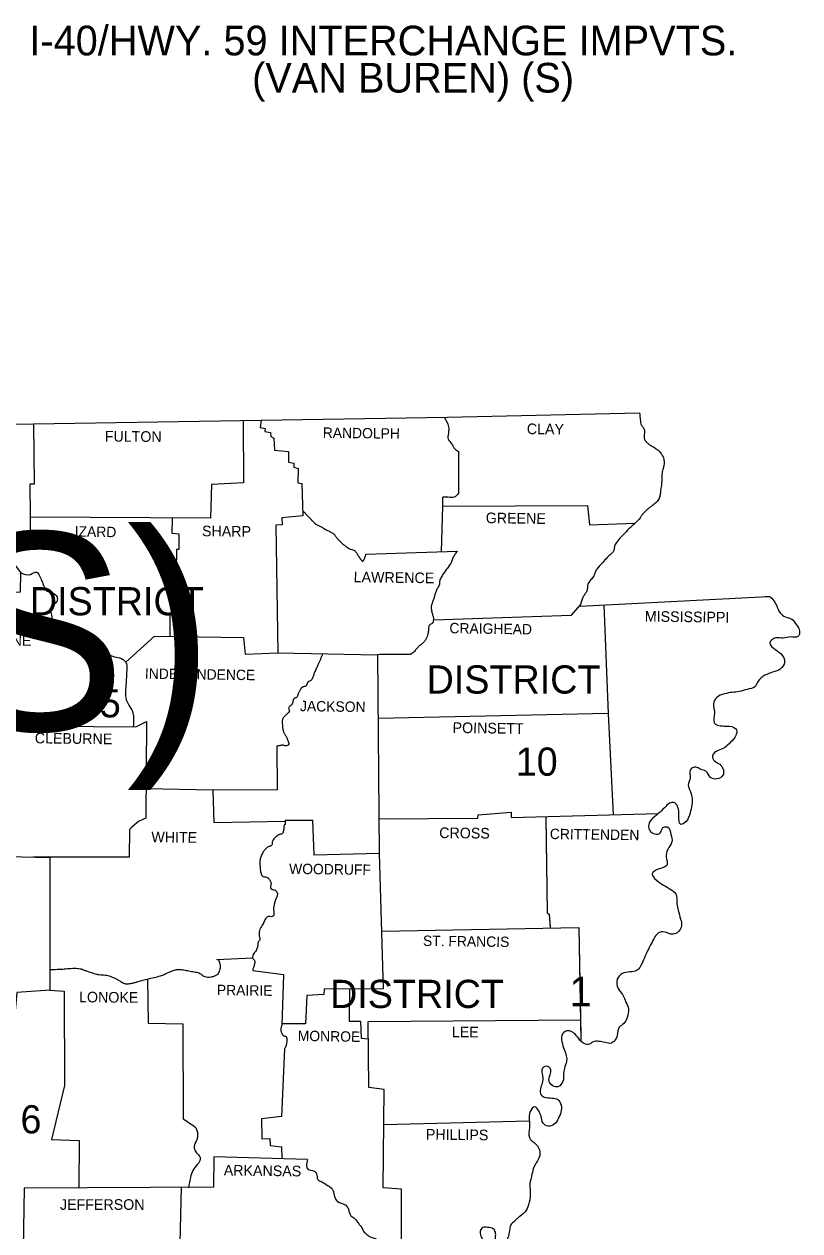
# Model space of a CAD drawing. Extents: x 535214 to 694517, y 381272 to 484355.
# Drawn here: x 674649 to 690329, y 455929 to 480321 of the extents above; entities that cross this region are included whole.
import ezdxf

# ---------------------------------------------------------------- set-up
doc = ezdxf.new("R2010")
doc.units = 0
for name, color, linetype in [('1', 7, 'Continuous'), ('Default', 7, 'Continuous'), ('G-ANNO-TEXT', 7, 'Continuous'), ('Level 8', 7, 'Continuous')]:
    doc.layers.add(name, color=color, linetype=linetype)

msp = doc.modelspace()

# ---------------------------------------------------------------- linework, layer by layer
at = {"layer": '1'}
for p, q in [((685889, 468559), (685943, 468725)), ((679929, 464229), (680488, 464229))]:
    msp.add_line(p, q, dxfattribs=at)
for points in [[(659659, 472234), (667744, 472229), (674839, 472244), (683209, 472374), (687089, 472464)], [(674839, 472244), (674849, 471024), (674764, 471019), (674779, 469774), (674429, 469724), (674459, 469389), (674579, 469234), (674569, 468839), (673889, 468814), (673864, 468204), (673244, 468184), (673214, 467444), (673249, 467384), (673264, 466204), (674334, 466134), (674319, 463499), (675169, 463474), (675169, 460794), (674499, 460744), (674449, 460154), (673324, 460149)], [(679438, 472315), (679419, 472164), (679519, 472149), (679514, 472089), (679629, 472064), (679639, 471984), (679694, 471949), (679709, 471709), (679994, 471679), (679994, 471464), (680099, 471449), (680099, 471364), (680189, 471339), (680184, 471049), (680264, 471034), (680284, 470379), (679859, 470339), (679864, 470199), (679734, 470194), (679779, 467614), (681794, 467569), (681829, 463559), (680514, 463524), (680488, 464229)], [(685889, 468559), (689684, 468754)], [(679929, 464229), (679929, 464144), (679904, 464139)], [(681823, 464259), (683819, 464269), (683824, 464339), (684494, 464389), (684494, 464284), (687473, 464366)], [(678544, 461414), (679264, 461449)], [(679269, 461189), (679894, 461109), (679859, 460089)], [(679914, 459609), (679854, 458239), (679444, 458194), (679454, 457789), (679619, 457794), (679624, 457654), (679849, 457629), (679857, 457388)], [(680374, 457374), (678484, 457424), (678474, 456809), (674650, 456794)]]:
    msp.add_lwpolyline(points, dxfattribs=at)
for points in [[(687089, 472464), (687094, 472409), (687100, 472353), (687106, 472299), (687114, 472244), (687126, 472213), (687146, 472185), (687168, 472158), (687184, 472129), (687191, 472078), (687185, 472023), (687181, 471969), (687184, 471943), (687194, 471919), (687232, 471870), (687279, 471829), (687315, 471805), (687352, 471784), (687389, 471763), (687424, 471739), (687497, 471675), (687527, 471637), (687541, 471616), (687554, 471594), (687573, 471551), (687583, 471509), (687587, 471466), (687584, 471424), (687576, 471380), (687563, 471337), (687552, 471293), (687544, 471249), (687542, 471200), (687540, 471151), (687538, 471102), (687534, 471054), (687514, 470884), (687505, 470806), (687497, 470767), (687492, 470748), (687484, 470729), (687432, 470659), (687364, 470604), (687336, 470581), (687307, 470559), (687278, 470537), (687249, 470514), (687144, 470409), (687125, 470382), (687108, 470353), (687091, 470324), (687069, 470299), (686939, 470179), (686809, 470054), (686704, 469944), (686676, 469911), (686649, 469876), (686624, 469840), (686599, 469804), (686584, 469766), (686577, 469725), (686568, 469684), (686561, 469665), (686549, 469649), (686522, 469620), (686492, 469593), (686463, 469567), (686434, 469539), (686344, 469439), (686224, 469304), (686205, 469273), (686191, 469238), (686179, 469203), (686164, 469169), (686138, 469129), (686106, 469092), (686075, 469054), (686049, 469014), (686039, 468978), (686036, 468939), (686033, 468900), (686024, 468864), (686008, 468833), (685988, 468803), (685968, 468774), (685949, 468744), (685943, 468725)], [(689629, 468749), (689684, 468754), (689854, 468574), (689929, 468424), (690039, 468339), (690164, 468294), (690259, 468179), (690324, 468054), (690289, 467944), (690149, 467934), (689994, 467909), (689844, 467914), (689724, 467814), (689834, 467679), (689979, 467554), (690019, 467419), (689939, 467289), (689779, 467219), (689624, 467159), (689484, 467039), (689419, 466924), (689264, 466874), (689104, 466829), (688964, 466814), (688804, 466784), (688649, 466709), (688584, 466579), (688604, 466394), (688599, 466199), (688764, 466134), (688909, 466129), (689049, 466054), (689034, 465944), (688929, 465804), (688804, 465694), (688679, 465639), (688564, 465534), (688604, 465429), (688709, 465359), (688784, 465244), (688774, 465139), (688654, 465064), (688524, 465094), (688429, 465219), (688319, 465259), (688224, 465304), (688114, 465239), (688114, 465094), (688074, 464939), (688109, 464824), (688154, 464664), (688149, 464544), (688109, 464374), (688024, 464199), (687924, 464144), (687884, 464334), (687864, 464489), (687804, 464579), (687724, 464584), (687619, 464509), (687504, 464394), (687359, 464269), (687274, 464144), (687319, 463989), (687429, 463949), (687514, 463979), (687559, 464079), (687644, 464094), (687724, 463939)], [(679904, 464139), (679901, 464097), (679898, 464056), (679891, 464015), (679886, 463994), (679883, 463984), (679879, 463974), (679863, 463956), (679838, 463947), (679809, 463940), (679796, 463936), (679784, 463929), (679726, 463877), (679674, 463819), (679665, 463795), (679663, 463768), (679660, 463741), (679649, 463719), (679640, 463711), (679630, 463706), (679605, 463698), (679580, 463691), (679559, 463679), (679536, 463655), (679514, 463630), (679493, 463603), (679474, 463574), (679440, 463503), (679419, 463429), (679415, 463354), (679419, 463279), (679423, 463236), (679429, 463193), (679439, 463151), (679446, 463130), (679454, 463109), (679478, 463089), (679513, 463083), (679549, 463079), (679579, 463064), (679589, 463053), (679599, 463041), (679615, 463016), (679639, 462964), (679641, 462938), (679633, 462911), (679627, 462884), (679629, 462859), (679653, 462837), (679687, 462825), (679723, 462813), (679749, 462789), (679758, 462774), (679766, 462759), (679770, 462744), (679769, 462729), (679749, 462664), (679694, 462479), (679691, 462448), (679693, 462417), (679698, 462385), (679699, 462354), (679697, 462326), (679694, 462313), (679689, 462299), (679663, 462280), (679623, 462280), (679583, 462280), (679554, 462264), (679474, 462129), (679419, 462034), (679413, 462019), (679402, 461972), (679401, 461940), (679399, 461909), (679402, 461886), (679408, 461864), (679414, 461841), (679414, 461819), (679408, 461800), (679396, 461783), (679383, 461767), (679374, 461749), (679371, 461723), (679370, 461696), (679367, 461669), (679359, 461644), (679309, 461554), (679264, 461469), (679266, 461444), (679286, 461420), (679307, 461395), (679314, 461369), (679307, 461334), (679299, 461299), (679292, 461271), (679283, 461244), (679269, 461189)], [(687724, 463939), (687744, 463794), (687659, 463639), (687629, 463484), (687644, 463329), (687484, 463244), (687344, 463144), (687424, 463024), (687574, 462914), (687724, 462829), (687819, 462744), (687844, 462539), (687869, 462409), (687919, 462229), (687939, 462104), (687849, 461954), (687744, 461924), (687634, 461959), (687504, 461969), (687399, 461869), (687324, 461729), (687249, 461589), (687194, 461469), (687139, 461339), (687029, 461189), (686894, 461164), (686734, 461124), (686639, 461014), (686654, 460829), (686744, 460704), (686814, 460549), (686864, 460414), (686839, 460244), (686769, 460119), (686679, 460044), (686639, 459884), (686574, 459764), (686514, 459724), (686394, 459734), (686264, 459759), (686154, 459749), (686049, 459694), (685944, 459729), (685834, 459849), (685744, 459939), (685644, 459974), (685539, 459919), (685519, 459754), (685569, 459584), (685614, 459354), (685569, 459214), (685554, 458984)], [(675169, 461213), (675459, 461224), (675734, 461234), (675823, 461216), (675866, 461200), (675888, 461191), (675909, 461184), (676109, 461119), (676138, 461112), (676167, 461108), (676227, 461104), (676286, 461100), (676344, 461089), (676509, 461024), (676534, 461012), (676558, 460997), (676606, 460966), (676679, 460929), (676691, 460926), (676704, 460924), (676735, 460923), (676829, 460935), (676892, 460952), (676954, 460969), (677149, 461019), (677404, 461084), (677447, 461098), (677488, 461116), (677528, 461136), (677569, 461154), (677593, 461164), (677663, 461192), (677711, 461207), (677735, 461212), (677759, 461214), (677854, 461206), (677949, 461189), (678057, 461170), (678164, 461149), (678201, 461134), (678234, 461111), (678266, 461087), (678299, 461069), (678358, 461057), (678422, 461061), (678486, 461077), (678516, 461089), (678544, 461104), (678575, 461132), (678597, 461173), (678617, 461274), (678600, 461367), (678578, 461399), (678544, 461414)], [(679859, 460089), (679854, 460077), (679849, 460064), (679843, 460039), (679840, 460014), (679839, 460001), (679839, 459989), (679843, 459962), (679852, 459936), (679864, 459909), (679872, 459897), (679879, 459884), (679886, 459877), (679895, 459872), (679916, 459867), (679936, 459862), (679944, 459857), (679947, 459853), (679949, 459849), (679952, 459843), (679954, 459837), (679962, 459799), (679962, 459774), (679961, 459761), (679959, 459749), (679950, 459699), (679943, 459674), (679939, 459661), (679934, 459649), (679925, 459629), (679914, 459609)], [(685554, 458984), (685439, 458839), (685269, 458929), (685269, 459049), (685294, 459174), (685234, 459254), (685129, 459219), (685129, 459064), (685119, 458914), (685089, 458699), (685159, 458634), (685319, 458614), (685434, 458584), (685504, 458469), (685499, 458329), (685444, 458194), (685364, 458084), (685239, 458044), (685139, 458109), (685099, 458239), (685054, 458354), (684969, 458439), (684879, 458344), (684859, 458169), (684864, 458019), (684864, 457814), (684994, 457679), (685074, 457524), (685049, 457384), (684954, 457219), (684914, 457074), (684874, 456879), (684879, 456664), (684844, 456454), (684774, 456314), (684644, 456199), (684559, 456124), (684489, 456049), (684454, 455899), (684429, 455794), (684334, 455669), (684259, 455659), (684199, 455709), (684179, 455794), (684179, 455879), (684139, 455964), (684014, 455999), (683914, 455994), (683869, 455924), (683934, 455729), (683959, 455604), (683924, 455434), (683944, 455414), (683764, 455319), (683619, 455304), (683499, 455269), (683384, 455194), (683329, 455084), (683249, 454994), (683179, 454909), (683084, 454869), (682979, 454889), (682839, 454904), (682759, 454804), (682784, 454659), (682879, 454574), (683019, 454534), (683164, 454544), (683304, 454559), (683434, 454489), (683409, 454354), (683284, 454289), (683099, 454269), (682949, 454284), (682769, 454244), (682679, 454129), (682729, 453954), (682924, 453884), (683014, 453719), (683019, 453564), (682954, 453359), (682864, 453264), (682689, 453224), (682554, 453199), (682534, 452969), (682474, 452854), (682369, 452819), (682219, 452894), (682129, 452929), (682019, 452979), (681879, 453064), (681774, 453049), (681804, 452829), (681814, 452819), (681934, 452654), (682054, 452524), (682109, 452369)], [(680374, 457374), (680389, 457169), (680509, 457139), (680559, 457084), (680584, 456969), (680669, 456919), (680784, 456849), (680854, 456799), (680904, 456719), (680934, 456589), (681014, 456504), (681124, 456464), (681204, 456369), (681254, 456234), (681334, 456174), (681414, 456069), (681454, 456024), (681524, 455904), (681594, 455844), (681644, 455809), (681724, 455784), (681824, 455719), (681889, 455619), (681889, 455544), (681864, 455429), (681844, 455309), (681834, 455174), (681824, 455054), (681869, 454954), (681844, 454804), (681794, 454724), (681789, 454614), (681774, 454449), (681754, 454354), (681709, 454199), (681644, 454119)]]:
    msp.add_spline(points, degree=3, dxfattribs=at)
at = {"layer": 'Default'}
msp.add_line((683110, 470574), (683114, 470759), dxfattribs=at)
for points in [[(679074, 472309), (679084, 471049), (678434, 471014), (678414, 470334), (674772, 470354)], [(683429, 471684), (683429, 470839)], [(683088, 469657), (683110, 470574), (683114, 470574), (686039, 470589), (686079, 470199), (686997, 470232)], [(677645, 470338), (677634, 470029), (677774, 470019), (677779, 469699), (677729, 469699), (677709, 468439), (677594, 468389), (677594, 467945)], [(681559, 469604), (683403, 469668)], [(682922, 468283), (685714, 468374), (685898, 468585)], [(686368, 468583), (686454, 466389), (686556, 464341)], [(676704, 467424), (677284, 467949), (679084, 467924), (679119, 467589), (679779, 467614)], [(682449, 467579), (681839, 467579), (681794, 467569)], [(686454, 466389), (681806, 466283)], [(674334, 466134), (676904, 466119), (677124, 466224), (677109, 464269), (676959, 464204), (676824, 464089), (676779, 464044), (676774, 463484), (674829, 463484)], [(679754, 465724), (679764, 464844), (678464, 464839), (677114, 464864)], [(678464, 464839), (678484, 464184), (679929, 464210)], [(685194, 464303), (685219, 462359), (685264, 462329), (685280, 462052)], [(685194, 464284), (685219, 462359), (685264, 462329), (685279, 462069)], [(685194, 464284), (685219, 462359), (685264, 462329), (685279, 462069)], [(685194, 464284), (685219, 462359), (685264, 462329), (685279, 462069)], [(685194, 464284), (685219, 462359), (685264, 462329), (685279, 462069)], [(681829, 463559), (681904, 460819), (680714, 460814), (680709, 460704), (680364, 460684), (680334, 460114), (679860, 460114)], [(681873, 461984), (685859, 462064)], [(685859, 462064), (685899, 459874)], [(685859, 462064), (685899, 459874)], [(685859, 462064), (685899, 459874)], [(685859, 462064), (685899, 459874)], [(685859, 462064), (685899, 459874)], [(685859, 462064), (685899, 459874)], [(685859, 462064), (685899, 459874)], [(685859, 462064), (685901, 459774)], [(677144, 461024), (677154, 460129), (677859, 460114), (677864, 458194)], [(675169, 460794), (675459, 460774), (675464, 458864), (675204, 457779), (675759, 457754), (675754, 456798)], [(681225, 460816), (681219, 460169), (681449, 460169), (681459, 459824), (681607, 459809)], [(681813, 455729), (682279, 455759), (682274, 456774), (681909, 456799), (681929, 458784), (681614, 458829), (681604, 460164), (685894, 460194)], [(681922, 458079), (684860, 458152)], [(674650, 456794), (674619, 454764), (674504, 454759), (674489, 453504)], [(677821, 456807), (677779, 454844), (678474, 454789)]]:
    msp.add_lwpolyline(points, dxfattribs=at)
for points in [[(683139, 472373), (683229, 472184), (683224, 472049), (683224, 471924), (683289, 471839), (683354, 471734), (683429, 471684)], [(683429, 470839), (683344, 470759), (683219, 470759), (683114, 470759)], [(680281, 470484), (680365, 470396), (680449, 470309), (680461, 470297), (680496, 470260), (680519, 470236), (680532, 470225), (680538, 470219), (680544, 470214), (680570, 470197), (680598, 470184), (680627, 470172), (680654, 470159), (680719, 470121), (680784, 470084), (680813, 470069), (680842, 470055), (680886, 470032), (680893, 470028), (680899, 470024), (680922, 470003), (680939, 469979), (680956, 469953), (680965, 469940), (680974, 469929), (681026, 469876), (681079, 469824), (681105, 469801), (681131, 469780), (681158, 469759), (681184, 469739), (681225, 469718), (681271, 469703), (681314, 469687), (681333, 469675), (681342, 469667), (681349, 469659), (681364, 469638), (681378, 469617), (681391, 469595), (681404, 469574), (681414, 469560), (681423, 469545), (681442, 469516), (681461, 469490), (681470, 469478), (681475, 469473), (681477, 469471), (681479, 469469), (681485, 469465), (681491, 469465), (681502, 469471), (681524, 469507), (681543, 469557), (681552, 469582), (681559, 469604)], [(683403, 469668), (683361, 469608), (683324, 469544), (683309, 469509), (683295, 469473), (683282, 469438), (683264, 469404), (683236, 469363), (683206, 469323), (683174, 469284), (683144, 469244), (683096, 469168), (683074, 469129), (683054, 469089), (683048, 469063), (683046, 469036), (683045, 469009), (683039, 468984), (683023, 468948), (683004, 468914), (682985, 468880), (682969, 468844), (682959, 468809), (682949, 468774), (682940, 468739), (682929, 468704), (682919, 468674), (682907, 468644), (682895, 468614), (682884, 468584), (682879, 468553), (682878, 468522), (682881, 468490), (682884, 468459), (682891, 468427), (682901, 468396), (682912, 468365), (682919, 468334), (682923, 468305), (682922, 468276), (682917, 468247), (682914, 468233), (682909, 468219), (682894, 468202), (682871, 468191), (682848, 468181), (682834, 468164), (682831, 468146), (682828, 468128), (682824, 468091), (682821, 468055), (682814, 468019), (682801, 467969), (682784, 467919), (682757, 467866), (682739, 467842), (682719, 467819), (682697, 467798), (682672, 467781), (682647, 467763), (682624, 467744), (682599, 467716), (682575, 467687), (682551, 467657), (682524, 467629), (682489, 467601), (682470, 467589), (682449, 467579)], [(674579, 469234), (674779, 469199), (674899, 469244), (674984, 469114), (675029, 469014), (675104, 468869), (675224, 468824), (675314, 468744), (675314, 468659), (675234, 468579), (675174, 468499), (675194, 468404), (675214, 468274), (675214, 468149), (675184, 468034), (675159, 467929), (675184, 467839), (675279, 467854), (675379, 467929), (675484, 467929), (675584, 467874), (675689, 467779), (675794, 467799), (675879, 467824), (675999, 467859), (676084, 467814), (676159, 467754), (676249, 467659), (676334, 467599), (676444, 467544), (676579, 467509), (676704, 467424), (676724, 467279), (676719, 467154), (676709, 466999), (676699, 466829), (676714, 466664), (676769, 466554), (676839, 466424), (676859, 466304), (676854, 466114)], [(680683, 467594), (680638, 467481), (680589, 467369), (680572, 467331), (680554, 467294), (680537, 467256), (680519, 467219), (680507, 467187), (680497, 467154), (680487, 467121), (680474, 467089), (680456, 467066), (680430, 467049), (680402, 467033), (680390, 467024), (680379, 467014), (680371, 466998), (680365, 466979), (680359, 466960), (680349, 466944), (680331, 466933), (680307, 466929), (680283, 466925), (680264, 466914), (680255, 466902), (680246, 466891), (680229, 466866), (680213, 466840), (680199, 466814), (680191, 466792), (680185, 466768), (680178, 466745), (680169, 466724), (680155, 466711), (680135, 466703), (680115, 466696), (680099, 466684), (680093, 466672), (680088, 466658), (680081, 466629), (680075, 466600), (680068, 466580), (680064, 466574), (680050, 466558), (680032, 466544), (680013, 466530), (679999, 466514), (679997, 466490), (680004, 466463), (680010, 466436), (680004, 466414), (680000, 466409), (679996, 466404), (679967, 466379), (679948, 466362), (679929, 466344), (679912, 466325), (679895, 466307), (679881, 466287), (679874, 466276), (679869, 466264), (679863, 466209), (679869, 466154), (679873, 466117), (679877, 466081), (679884, 466045), (679889, 466027), (679894, 466009), (679905, 465986), (679918, 465966), (679932, 465945), (679944, 465924), (679969, 465869), (679980, 465842), (679989, 465814), (679995, 465796), (679998, 465777), (679996, 465759), (679991, 465751), (679988, 465747), (679984, 465744), (679954, 465732), (679922, 465735), (679891, 465743), (679875, 465745), (679859, 465744), (679833, 465740), (679807, 465735), (679781, 465730), (679754, 465724)], [(677864, 458194), (677989, 458109), (678119, 458009), (678154, 457874), (678144, 457779), (678104, 457699), (678094, 457574), (678154, 457484), (678209, 457409), (678154, 457274), (678059, 457149), (678009, 457009), (677974, 456799)]]:
    msp.add_spline(points, degree=3, dxfattribs=at)

# ---------------------------------------------------------------- texts
for s, height, rotation, p in [('CLAY', 215, 359.2258, (684809, 472034)), ('FULTON', 215, 359.4996, (676279, 471884)), ('RANDOLPH', 210, 359.2584, (680684, 471959)), ('GREENE', 215, 359.2361, (683979, 470234)), ('IZARD', 210, 358.9259, (675669, 469964)), ('SHARP', 215, 359.3905, (678244, 469969)), ('LAWRENCE', 215, 359.2678, (681309, 469039)), ('MISSISSIPPI', 214.97, 359.3097, (687194, 468244)), ('CRAIGHEAD', 210, 359.1159, (683244, 468009)), ('STONE', 210, 359.4001, (673824, 467764)), ('INDEPENDENCE', 209.96, 359.2188, (677089, 467089)), ('JACKSON', 210, 359.1352, (680224, 466434)), ('POINSETT', 215, 359.1987, (683309, 465994)), ('CLEBURNE', 215, 359.2535, (674864, 465784)), ('WHITE', 215, 359.3139, (677219, 463784)), ('CROSS', 215, 359.384, (683039, 463869)), ('CRITTENDEN', 210, 359.213, (685274, 463849)), ('WOODRUFF', 210, 359.2748, (680004, 463144)), ('ST. FRANCIS', 209.96, 359.2216, (682709, 461689)), ('LONOKE', 215, 359.4974, (675759, 460549)), ('PRAIRIE', 210, 359.2116, (678544, 460694)), ('LEE', 215, 359.4327, (683294, 459844)), ('MONROE', 210, 359.0331, (680179, 459769)), ('PHILLIPS', 215, 359.318, (682769, 457774)), ('ARKANSAS', 215, 359.2678, (678684, 457049))]:
    msp.add_text(s, height=height, rotation=rotation, dxfattribs=at).set_placement(p)
for s, height, p in [('DISTRICT', 570, (674765, 468371)), ('DISTRICT', 570, (682784, 466789)), ('5', 570, (676179, 466307)), ('10', 570, (684586, 465129)), ('DISTRICT', 570, (680834, 460434)), ('1', 600, (685674, 460469)), ('DISTRICT 6', 570, (670849, 457899)), ('JEFFERSON', 215, (675374, 456354))]:
    msp.add_text(s, height=height, dxfattribs=at).set_placement(p)
at = {"layer": 'G-ANNO-TEXT'}
for s, p in [('I-40/HWY. 59 INTERCHANGE IMPVTS. ', (674755, 479689)), ('(VAN BUREN) (S)', (679257, 478937))]:
    msp.add_text(s, height=600, dxfattribs=at).set_placement(p)
at = {"layer": 'Level 8'}
msp.add_text('INTERCHANGE IMPVTS. (VAN BUREN) (S)', height=4000, dxfattribs=at).set_placement((571808, 466045))

doc.saveas('drawing.dxf')
